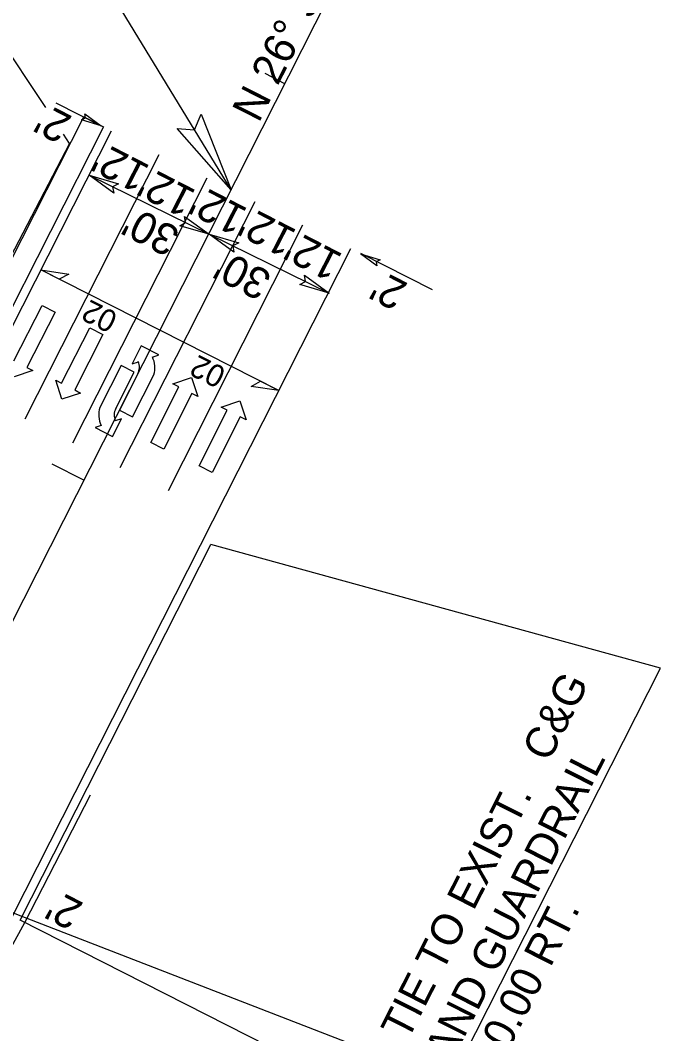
# Model space of a CAD drawing. Extents: x 1974386 to 1979988, y 776712 to 784860.
# Drawn here: x 1977928 to 1978072.7, y 782158.9 to 782386.9 of the extents above; entities that cross this region are included whole.
import ezdxf

# ---------------------------------------------------------------- set-up
doc = ezdxf.new("R2010")
doc.units = 0
for name, color, linetype in [('Old_Level_11', 7, 'Continuous'), ('Prop Conc 2ft 6in Curb and Gutter', 7, 'Continuous'), ('Prop Conc 4in Sidewalk', 7, 'Continuous'), ('Prop Dimension', 7, 'Continuous'), ('Prop Dimension Text', 7, 'Continuous'), ('Prop DSN Text', 7, 'Continuous'), ('Prop EOT', 7, 'Continuous'), ('Prop Guardrail', 7, 'Continuous'), ('Prop Horizontal Alignment', 7, 'Continuous'), ('Prop Horizontal Alignment Direction Label', 7, 'Continuous'), ('Prop Horizontal Alignment Tick Large', 7, 'Continuous'), ('Prop Horizontal Alignment Tick Small', 7, 'Continuous'), ('Prop Lane Arrow CELL', 7, 'Continuous'), ('Prop Lane Lines', 7, 'Continuous'), ('Prop Superelevation  Arrow CELL', 7, 'Continuous'), ('Prop Superelevation Label', 7, 'Continuous'), ('Prop Terminator CELL', 7, 'Continuous'), ('Sheet Layout Plan Border', 7, 'Continuous')]:
    doc.layers.add(name, color=color, linetype=linetype)

msp = doc.modelspace()

# ---------------------------------------------------------------- linework, layer by layer
at = {"layer": 'Old_Level_11'}
msp.add_line((1977975.39, 782348.76), (1977787.3, 782657.18), dxfattribs=at)
msp.add_lwpolyline([(1977968.66, 782365.74), (1977975.39, 782348.76), (1977963.23, 782362.54), (1977967.16, 782362.25)], close=True, dxfattribs=at)
at = {"layer": 'Prop Conc 2ft 6in Curb and Gutter'}
msp.add_line((1977927.97, 782184.44), (1977970.8, 782268.93), dxfattribs=at)
at = {"layer": 'Prop Conc 4in Sidewalk'}
for p, q in [((1977866.43, 782215.64), (1977942.22, 782365.15)), ((1977942.22, 782365.15), (1977946.67, 782362.89)), ((1977946.67, 782362.89), (1977870.89, 782213.38))]:
    msp.add_line(p, q, dxfattribs=at)
at = {"layer": 'Prop Dimension'}
for p, q in [((1977935.92, 782368.27), (1977946.14, 782363.14)), ((1977943.42, 782352.02), (1977970.47, 782338.74)), ((1977970.47, 782338.74), (1977997.47, 782325.48)), ((1978020.71, 782326.21), (1978004.53, 782334.42)), ((1977942.26, 782283.4), (1977942.26, 782283.4)), ((1977937.21, 782179.76), (1977927.97, 782184.44)), ((1977994.25, 782150.84), (1977937.21, 782179.76))]:
    msp.add_line(p, q, dxfattribs=at)
at = {"layer": 'Prop DSN Text'}
for p, q in [((1977933.68, 782367.22), (1977839.3, 782509.19)), ((1977939.06, 782359.12), (1977937.67, 782361.22)), ((1978071.95, 782241.16), (1977970.8, 782268.93)), ((1978024.77, 782148.13), (1978071.95, 782241.16))]:
    msp.add_line(p, q, dxfattribs=at)
at = {"layer": 'Prop EOT'}
for p, q in [((1977872.67, 782212.47), (1977948.46, 782361.98)), ((1977926.19, 782185.34), (1978002.32, 782335.53))]:
    msp.add_line(p, q, dxfattribs=at)
at = {"layer": 'Prop Guardrail'}
for p, q in [((1977939.06, 782359.12), (1977879.49, 782245.27)), ((1977928.99, 782183.92), (1977943.79, 782212.67)), ((1977862.8, 782064.15), (1977928.99, 782183.92))]:
    msp.add_line(p, q, dxfattribs=at)
at = {"layer": 'Prop Horizontal Alignment'}
msp.add_line((1977839.03, 782079.75), (1978119.82, 782633.69), dxfattribs=at)
at = {"layer": 'Prop Horizontal Alignment Tick Large'}
msp.add_line((1977942.26, 782283.4), (1977935.12, 782287.02), dxfattribs=at)
at = {"layer": 'Prop Horizontal Alignment Tick Small'}
msp.add_line((1977987.47, 782372.59), (1977983.01, 782374.86), dxfattribs=at)
at = {"layer": 'Prop Lane Arrow CELL'}
for p, q in [((1977926.53, 782310.25), (1977932.88, 782322.72)), ((1977932.88, 782322.72), (1977935.82, 782321.23)), ((1977935.82, 782321.23), (1977929.47, 782308.75)), ((1977937.26, 782305.21), (1977943.61, 782317.68)), ((1977943.61, 782317.68), (1977946.55, 782316.18)), ((1977946.55, 782316.18), (1977940.2, 782303.71)), ((1977955.14, 782313.63), (1977953.11, 782309.62)), ((1977959.11, 782311.62), (1977955.14, 782313.63)), ((1977953.11, 782309.62), (1977954.52, 782310.08)), ((1977957.68, 782311.11), (1977959.11, 782311.62)), ((1977930.8, 782308.07), (1977926.61, 782306.67)), ((1977929.47, 782308.75), (1977930.8, 782308.07)), ((1977950.64, 782309.19), (1977945.87, 782299.78)), ((1977953.59, 782307.69), (1977950.64, 782309.19)), ((1977937.34, 782301.63), (1977935.92, 782305.89)), ((1977935.92, 782305.89), (1977937.26, 782305.21)), ((1977949.45, 782299.53), (1977953.59, 782307.69)), ((1977954.41, 782307.33), (1977950.27, 782299.17)), ((1977953.22, 782297.68), (1977957.99, 782307.09)), ((1977962.26, 782305.07), (1977966.44, 782306.5)), ((1977966.44, 782306.5), (1977967.89, 782302.25)), ((1977940.2, 782303.71), (1977941.53, 782303.03)), ((1977957.33, 782291.88), (1977963.6, 782304.4)), ((1977963.6, 782304.4), (1977962.26, 782305.07)), ((1977941.53, 782303.03), (1977937.34, 782301.63)), ((1977966.55, 782302.92), (1977960.28, 782290.4)), ((1977967.89, 782302.25), (1977966.55, 782302.92)), ((1977973.13, 782299.82), (1977977.32, 782301.24)), ((1977977.32, 782301.24), (1977978.76, 782296.99)), ((1977950.27, 782299.17), (1977953.22, 782297.68)), ((1977968.16, 782286.65), (1977974.47, 782299.15)), ((1977974.47, 782299.15), (1977973.13, 782299.82)), ((1977948.67, 782293.26), (1977950.75, 782297.25)), ((1977950.75, 782297.25), (1977949.34, 782296.78)), ((1977977.42, 782297.66), (1977971.11, 782285.16)), ((1977978.76, 782296.99), (1977977.42, 782297.66)), ((1977946.18, 782295.75), (1977944.77, 782295.29)), ((1977944.77, 782295.29), (1977948.67, 782293.26)), ((1977960.28, 782290.4), (1977957.33, 782291.88)), ((1977971.11, 782285.16), (1977968.16, 782286.65))]:
    msp.add_line(p, q, dxfattribs=at)
for centre, radius, start, end in [((1977951.49, 782308.84), 3.27, 333.1044, 22.7626), ((1977952.99, 782308.75), 5.25, 341.7805, 27.0922), ((1977950.85, 782298.14), 5.25, 161.7805, 207.0922), ((1977952.35, 782298.05), 3.27, 153.1044, 202.7626)]:
    msp.add_arc(centre, radius, start, end, dxfattribs=at)
at = {"layer": 'Prop Lane Lines'}
for p, q in [((1977929.09, 782297.23), (1977959.23, 782356.69)), ((1977939.79, 782291.8), (1977970, 782351.4)), ((1977950.45, 782286.28), (1977980.77, 782346.11)), ((1977961.27, 782281.09), (1977991.55, 782340.82))]:
    msp.add_line(p, q, dxfattribs=at)
at = {"layer": 'Prop Superelevation  Arrow CELL'}
for points in [[(1977932.6, 782330.7), (1977938.86, 782329.77), (1977936.73, 782328.61)], [(1977986.12, 782303.57), (1977979.86, 782304.5), (1977981.99, 782305.66)]]:
    msp.add_lwpolyline(points, close=True, dxfattribs=at)
at = {"layer": 'Prop Superelevation Label'}
msp.add_line((1977986.12, 782303.57), (1977932.6, 782330.7), dxfattribs=at)
at = {"layer": 'Prop Terminator CELL'}
for points in [[(1977942.47, 782365.85), (1977946.14, 782363.14), (1977941.74, 782364.46), (1977942.61, 782364.91)], [(1977948.97, 782348), (1977943.42, 782352.02), (1977950.05, 782350.11), (1977948.74, 782349.41)], [(1977964.92, 782342.76), (1977970.47, 782338.74), (1977963.85, 782340.66), (1977965.15, 782341.35)], [(1977976.02, 782334.72), (1977970.47, 782338.74), (1977977.09, 782336.83), (1977975.79, 782336.13)], [(1978008.15, 782331.62), (1978004.49, 782334.34), (1978008.89, 782333.01), (1978008.01, 782332.56)], [(1977991.92, 782329.5), (1977997.47, 782325.48), (1977990.85, 782327.4), (1977992.15, 782328.1)]]:
    msp.add_lwpolyline(points, close=True, dxfattribs=at)
at = {"layer": 'Sheet Layout Plan Border'}
msp.add_lwpolyline([(1977881.86, 780701.89), (1978387.67, 782007.32), (1977408.59, 782386.68), (1976902.78, 781081.25)], close=True, dxfattribs=at)

# ---------------------------------------------------------------- texts
at = {"layer": 'Prop Dimension Text'}
for s, rotation, p in [("2'", 152.7847, (1977939.93, 782365.12)), ("12'", 152.7847, (1977957.45, 782354)), ("12'", 152.7847, (1977967.83, 782348.44)), ("12'", 152.7847, (1977979.42, 782344.35)), ("30'", 152.7847, (1977964.3, 782339.68)), ("12'", 152.7847, (1977990.46, 782339.5)), ("12'", 152.7847, (1978000.82, 782334.1)), ("30'", 152.7847, (1977984.93, 782329.82)), ("2'", 152.7847, (1978015.44, 782327.56)), ('TIE TO EXIST.   C&G', 63.1199, (1978015.08, 782157.15)), ('AND GUARDRAIL', 63.1199, (1978024.89, 782152.18)), ("2'", 152.7847, (1977942.47, 782188.19)), ('+00.00 RT.', 63.1199, (1978032.96, 782145.57))]:
    msp.add_text(s, height=7, rotation=rotation, dxfattribs=at).set_placement(p)
at = {"layer": 'Prop Horizontal Alignment Direction Label'}
msp.add_text('N 26%%d 52\' 48.5" E', height=7, rotation=63.1199, dxfattribs=at).set_placement((1977981.6, 782363.61))
at = {"layer": 'Prop Superelevation Label'}
for p in [(1977950.2, 782320.82), (1977974.54, 782308.4)]:
    msp.add_text('02', height=5, rotation=153.1199, dxfattribs=at).set_placement(p)

doc.saveas('drawing.dxf')
